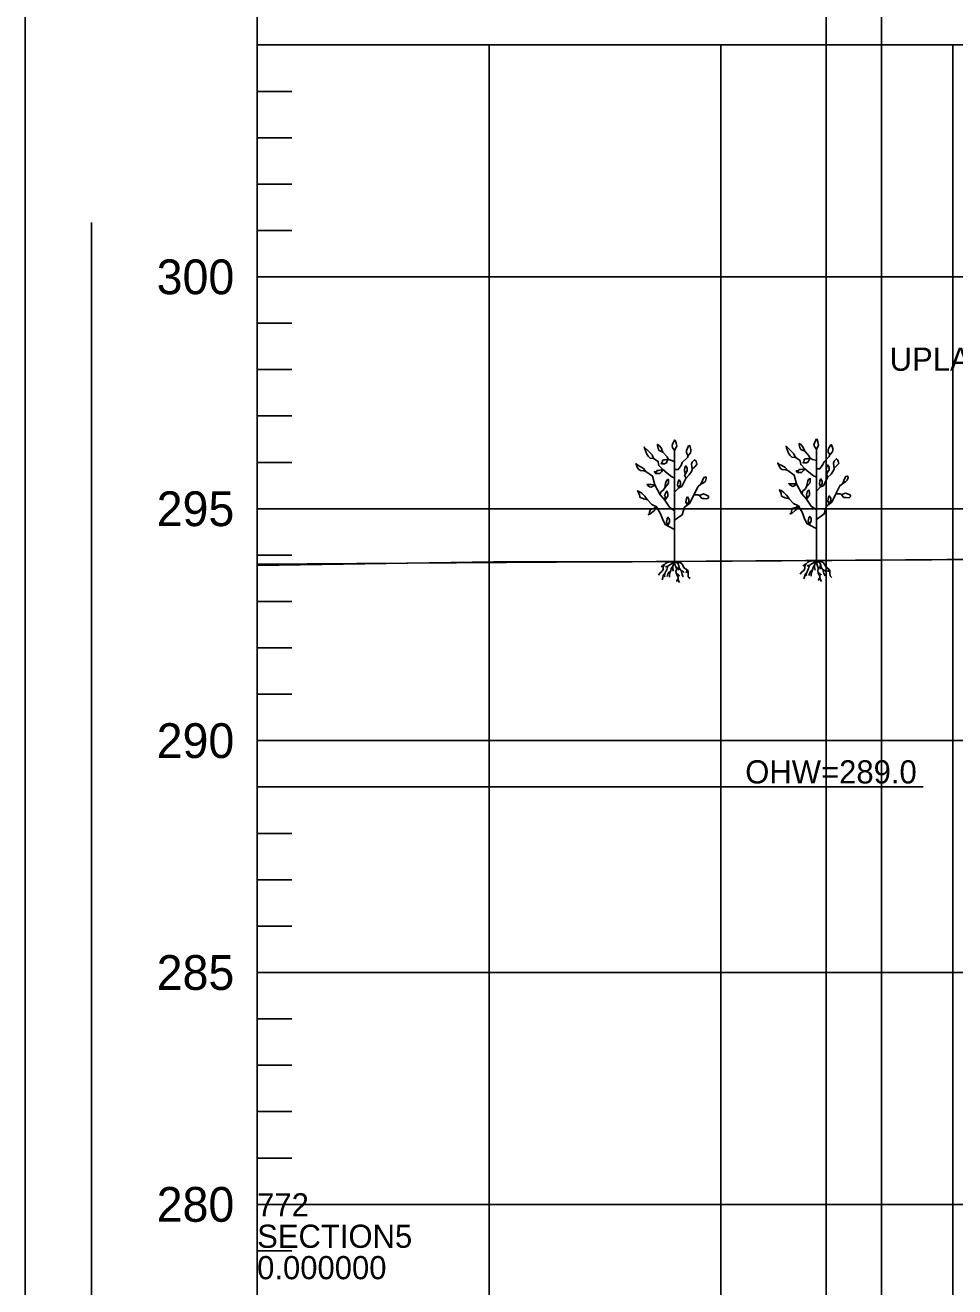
# Model space of a CAD drawing. Extents: x 1578769 to 1579225, y 724002 to 724828.
# Drawn here: x 1578822.77 to 1578842.81, y 724530.2 to 724557.4 of the extents above; entities that cross this region are included whole.
import ezdxf

# ---------------------------------------------------------------- set-up
doc = ezdxf.new("R2010")
doc.units = 0
for name, color, linetype in [('1', 7, 'Continuous'), ('Default', 7, 'Continuous'), ('Old_Level_1', 7, 'Continuous'), ('Old_Level_41', 7, 'Continuous'), ('Old_Level_42', 7, 'Continuous'), ('R_Exist Surface', 7, 'Continuous')]:
    doc.layers.add(name, color=color, linetype=linetype)

msp = doc.modelspace()

# ---------------------------------------------------------------- linework, layer by layer
at = {"layer": '1'}
for p, q in [((1578836.768, 724545.835), (1578836.768, 724548.235)), ((1578839.826, 724545.855), (1578839.826, 724548.255)), ((1578836.773, 724545.83), (1578836.775, 724545.834)), ((1578839.83, 724545.85), (1578839.832, 724545.854)), ((1578827.766, 724540.976), (1578842.126, 724540.976))]:
    msp.add_line(p, q, dxfattribs=at)
for points in [[(1578836.768, 724548.235), (1578836.724, 724548.299), (1578836.711, 724548.324), (1578836.724, 724548.374), (1578836.737, 724548.4), (1578836.762, 724548.456), (1578836.781, 724548.45), (1578836.8, 724548.4), (1578836.806, 724548.362), (1578836.812, 724548.324)], [(1578839.826, 724548.255), (1578839.781, 724548.319), (1578839.769, 724548.344), (1578839.781, 724548.394), (1578839.794, 724548.42), (1578839.819, 724548.476), (1578839.838, 724548.47), (1578839.857, 724548.42), (1578839.863, 724548.382), (1578839.87, 724548.344)], [(1578836.314, 724548.059), (1578836.238, 724548.065), (1578836.194, 724548.109), (1578836.169, 724548.153), (1578836.125, 724548.267), (1578836.112, 724548.305), (1578836.188, 724548.235), (1578836.232, 724548.191), (1578836.282, 724548.141)], [(1578836.516, 724548.197), (1578836.434, 724548.235), (1578836.409, 724548.273), (1578836.396, 724548.336), (1578836.396, 724548.362), (1578836.434, 724548.343), (1578836.478, 724548.292)], [(1578839.371, 724548.079), (1578839.295, 724548.085), (1578839.251, 724548.129), (1578839.226, 724548.173), (1578839.182, 724548.287), (1578839.169, 724548.325), (1578839.245, 724548.255), (1578839.289, 724548.211), (1578839.34, 724548.161)], [(1578839.573, 724548.217), (1578839.491, 724548.255), (1578839.466, 724548.293), (1578839.453, 724548.356), (1578839.453, 724548.382), (1578839.491, 724548.363), (1578839.535, 724548.312)], [(1578836.629, 724548.046), (1578836.561, 724548.031), (1578836.532, 724548.031), (1578836.504, 724548.022), (1578836.504, 724547.984), (1578836.475, 724547.955), (1578836.494, 724547.945), (1578836.551, 724547.945), (1578836.589, 724547.964), (1578836.609, 724548.012)], [(1578839.687, 724548.066), (1578839.618, 724548.051), (1578839.589, 724548.051), (1578839.561, 724548.042), (1578839.561, 724548.004), (1578839.532, 724547.975), (1578839.551, 724547.965), (1578839.609, 724547.965), (1578839.647, 724547.984), (1578839.666, 724548.032)], [(1578836.516, 724547.819), (1578836.475, 724547.812), (1578836.418, 724547.802), (1578836.389, 724547.802), (1578836.379, 724547.773), (1578836.332, 724547.773), (1578836.36, 724547.735), (1578836.399, 724547.735), (1578836.446, 724547.735), (1578836.484, 724547.773)], [(1578839.573, 724547.839), (1578839.532, 724547.832), (1578839.475, 724547.822), (1578839.446, 724547.822), (1578839.437, 724547.793), (1578839.389, 724547.793), (1578839.418, 724547.755), (1578839.456, 724547.755), (1578839.504, 724547.755), (1578839.542, 724547.793)], [(1578839.611, 724547.447), (1578839.63, 724547.542), (1578839.643, 724547.58), (1578839.649, 724547.599), (1578839.674, 724547.624), (1578839.693, 724547.624), (1578839.693, 724547.554), (1578839.68, 724547.529)], [(1578836.179, 724547.171), (1578836.093, 724547.191), (1578836.017, 724547.229), (1578836.007, 724547.286), (1578835.969, 724547.363), (1578836.026, 724547.334), (1578836.064, 724547.305), (1578836.122, 724547.248), (1578836.15, 724547.21)], [(1578836.554, 724547.162), (1578836.561, 724547.238), (1578836.551, 724547.257), (1578836.57, 724547.315), (1578836.599, 724547.353), (1578836.609, 724547.353), (1578836.618, 724547.296), (1578836.618, 724547.248)], [(1578836.554, 724547.427), (1578836.573, 724547.522), (1578836.585, 724547.56), (1578836.592, 724547.579), (1578836.617, 724547.604), (1578836.636, 724547.604), (1578836.636, 724547.534), (1578836.623, 724547.509)], [(1578839.236, 724547.191), (1578839.15, 724547.211), (1578839.074, 724547.249), (1578839.064, 724547.306), (1578839.026, 724547.383), (1578839.084, 724547.354), (1578839.122, 724547.325), (1578839.179, 724547.268), (1578839.208, 724547.23)], [(1578839.611, 724547.182), (1578839.618, 724547.258), (1578839.609, 724547.277), (1578839.628, 724547.335), (1578839.656, 724547.373), (1578839.666, 724547.373), (1578839.675, 724547.316), (1578839.675, 724547.268)], [(1578836.379, 724547.019), (1578836.322, 724546.98), (1578836.246, 724546.961), (1578836.227, 724546.904), (1578836.227, 724546.866), (1578836.198, 724546.847), (1578836.236, 724546.856), (1578836.313, 724546.923), (1578836.322, 724546.923), (1578836.379, 724546.99)], [(1578839.437, 724547.039), (1578839.379, 724547), (1578839.303, 724546.981), (1578839.284, 724546.924), (1578839.284, 724546.886), (1578839.255, 724546.867), (1578839.294, 724546.876), (1578839.37, 724546.943), (1578839.379, 724546.943), (1578839.437, 724547.01)]]:
    msp.add_lwpolyline(points, close=True, dxfattribs=at)
for points in [[(1578836.768, 724547.995), (1578836.68, 724548.021), (1578836.629, 724548.046), (1578836.604, 724548.096), (1578836.528, 724548.185), (1578836.516, 724548.197)], [(1578837.055, 724548.122), (1578837.024, 724548.179), (1578837.024, 724548.235), (1578837.043, 724548.28), (1578837.068, 724548.33), (1578837.093, 724548.336), (1578837.119, 724548.254), (1578837.119, 724548.216), (1578837.112, 724548.185), (1578837.062, 724548.122)], [(1578839.826, 724548.015), (1578839.737, 724548.041), (1578839.687, 724548.066), (1578839.661, 724548.116), (1578839.586, 724548.205), (1578839.573, 724548.217)], [(1578840.113, 724548.142), (1578840.081, 724548.199), (1578840.081, 724548.255), (1578840.1, 724548.3), (1578840.125, 724548.35), (1578840.151, 724548.356), (1578840.176, 724548.274), (1578840.176, 724548.236), (1578840.169, 724548.205), (1578840.119, 724548.142)], [(1578836.15, 724547.781), (1578836.106, 724547.793), (1578836.03, 724547.8), (1578835.998, 724547.819), (1578835.96, 724547.875), (1578835.935, 724547.939), (1578835.935, 724547.945), (1578835.973, 724547.913), (1578836.024, 724547.888), (1578836.093, 724547.844), (1578836.15, 724547.781)], [(1578836.756, 724547.642), (1578836.705, 724547.667), (1578836.604, 724547.743), (1578836.516, 724547.819), (1578836.427, 724547.907), (1578836.415, 724547.983), (1578836.415, 724547.995), (1578836.314, 724548.059)], [(1578836.768, 724547.819), (1578836.844, 724547.819), (1578836.907, 724547.907), (1578836.932, 724547.97), (1578837.046, 724548.084), (1578837.059, 724548.122)], [(1578837.002, 724547.73), (1578836.977, 724547.793), (1578836.989, 724547.869), (1578837.008, 724547.901), (1578837.04, 724547.85), (1578837.04, 724547.793), (1578837.002, 724547.73)], [(1578837.147, 724547.819), (1578837.134, 724547.939), (1578837.147, 724547.983), (1578837.197, 724548.033), (1578837.229, 724548.002), (1578837.248, 724547.932), (1578837.204, 724547.882), (1578837.147, 724547.831)], [(1578839.207, 724547.801), (1578839.163, 724547.813), (1578839.087, 724547.82), (1578839.056, 724547.839), (1578839.018, 724547.895), (1578838.992, 724547.959), (1578838.992, 724547.965), (1578839.03, 724547.933), (1578839.081, 724547.908), (1578839.15, 724547.864), (1578839.207, 724547.801)], [(1578839.813, 724547.662), (1578839.762, 724547.687), (1578839.661, 724547.763), (1578839.573, 724547.839), (1578839.485, 724547.927), (1578839.472, 724548.003), (1578839.472, 724548.015), (1578839.371, 724548.079)], [(1578839.826, 724547.839), (1578839.901, 724547.839), (1578839.964, 724547.927), (1578839.99, 724547.99), (1578840.103, 724548.104), (1578840.116, 724548.142)], [(1578840.059, 724547.75), (1578840.034, 724547.813), (1578840.046, 724547.889), (1578840.065, 724547.921), (1578840.097, 724547.87), (1578840.097, 724547.813), (1578840.059, 724547.75)], [(1578840.204, 724547.839), (1578840.192, 724547.959), (1578840.204, 724548.003), (1578840.255, 724548.053), (1578840.286, 724548.022), (1578840.305, 724547.952), (1578840.261, 724547.902), (1578840.204, 724547.851)], [(1578836.768, 724546.934), (1578836.655, 724547.01), (1578836.554, 724547.162), (1578836.453, 724547.275), (1578836.339, 724547.49), (1578836.289, 724547.68), (1578836.15, 724547.781)], [(1578836.768, 724547.351), (1578836.781, 724547.351), (1578836.857, 724547.427), (1578836.92, 724547.452), (1578837.008, 724547.629), (1578837.084, 724547.705), (1578837.134, 724547.781), (1578837.147, 724547.819)], [(1578837.008, 724547.629), (1578837.002, 724547.667), (1578836.983, 724547.692), (1578837.002, 724547.73)], [(1578837.336, 724547.503), (1578837.368, 724547.585), (1578837.399, 724547.648), (1578837.444, 724547.661), (1578837.45, 724547.629), (1578837.431, 724547.572), (1578837.393, 724547.534), (1578837.336, 724547.503)], [(1578839.826, 724546.954), (1578839.712, 724547.03), (1578839.611, 724547.182), (1578839.51, 724547.295), (1578839.396, 724547.51), (1578839.346, 724547.7), (1578839.207, 724547.801)], [(1578839.826, 724547.371), (1578839.838, 724547.371), (1578839.914, 724547.447), (1578839.977, 724547.472), (1578840.065, 724547.649), (1578840.141, 724547.725), (1578840.192, 724547.801), (1578840.204, 724547.839)], [(1578839.914, 724547.447), (1578839.889, 724547.51), (1578839.901, 724547.586), (1578839.92, 724547.618), (1578839.952, 724547.567), (1578839.952, 724547.51), (1578839.914, 724547.447)], [(1578840.065, 724547.649), (1578840.059, 724547.687), (1578840.04, 724547.712), (1578840.059, 724547.75)], [(1578840.394, 724547.523), (1578840.425, 724547.605), (1578840.457, 724547.668), (1578840.501, 724547.681), (1578840.507, 724547.649), (1578840.488, 724547.592), (1578840.45, 724547.554), (1578840.394, 724547.523)], [(1578836.339, 724547.49), (1578836.265, 724547.496), (1578836.208, 724547.496), (1578836.169, 724547.496), (1578836.189, 724547.477), (1578836.227, 724547.449), (1578836.265, 724547.439), (1578836.341, 724547.487)], [(1578836.453, 724547.275), (1578836.472, 724547.339), (1578836.522, 724547.376), (1578836.554, 724547.427)], [(1578836.768, 724546.727), (1578836.932, 724546.846), (1578836.983, 724547.01), (1578837.096, 724547.099), (1578837.185, 724547.275), (1578837.273, 724547.452), (1578837.336, 724547.503)], [(1578836.857, 724547.427), (1578836.831, 724547.49), (1578836.844, 724547.566), (1578836.863, 724547.598), (1578836.894, 724547.547), (1578836.894, 724547.49), (1578836.857, 724547.427)], [(1578839.396, 724547.51), (1578839.322, 724547.516), (1578839.265, 724547.516), (1578839.227, 724547.516), (1578839.246, 724547.497), (1578839.284, 724547.469), (1578839.322, 724547.459), (1578839.399, 724547.507)], [(1578839.51, 724547.295), (1578839.529, 724547.359), (1578839.579, 724547.396), (1578839.611, 724547.447)], [(1578839.826, 724546.747), (1578839.99, 724546.866), (1578840.04, 724547.03), (1578840.154, 724547.119), (1578840.242, 724547.295), (1578840.33, 724547.472), (1578840.394, 724547.523)], [(1578836.771, 724546.531), (1578836.733, 724546.541), (1578836.656, 724546.589), (1578836.561, 724546.636), (1578836.504, 724546.761), (1578836.465, 724546.866), (1578836.379, 724547.019), (1578836.274, 724547.066), (1578836.179, 724547.171), (1578836.179, 724547.171)], [(1578837.038, 724547.061), (1578837.012, 724547.125), (1578837.025, 724547.2), (1578837.044, 724547.232), (1578837.075, 724547.181), (1578837.075, 724547.125), (1578837.038, 724547.061)], [(1578837.185, 724547.275), (1578837.248, 724547.275), (1578837.273, 724547.275), (1578837.305, 724547.263)], [(1578837.305, 724547.263), (1578837.393, 724547.294), (1578837.456, 724547.269), (1578837.5, 724547.25), (1578837.5, 724547.219), (1578837.481, 724547.2), (1578837.45, 724547.193), (1578837.406, 724547.2), (1578837.355, 724547.2), (1578837.305, 724547.263)], [(1578839.828, 724546.551), (1578839.79, 724546.561), (1578839.714, 724546.609), (1578839.618, 724546.656), (1578839.561, 724546.781), (1578839.523, 724546.886), (1578839.437, 724547.039), (1578839.332, 724547.086), (1578839.236, 724547.191), (1578839.236, 724547.191)], [(1578840.095, 724547.081), (1578840.07, 724547.145), (1578840.082, 724547.22), (1578840.101, 724547.252), (1578840.133, 724547.201), (1578840.133, 724547.145), (1578840.095, 724547.081)], [(1578840.242, 724547.295), (1578840.305, 724547.295), (1578840.33, 724547.295), (1578840.362, 724547.283)], [(1578840.362, 724547.283), (1578840.45, 724547.314), (1578840.513, 724547.289), (1578840.558, 724547.27), (1578840.558, 724547.239), (1578840.539, 724547.22), (1578840.507, 724547.213), (1578840.463, 724547.22), (1578840.412, 724547.22), (1578840.362, 724547.283)], [(1578839.675, 724546.642), (1578839.65, 724546.705), (1578839.662, 724546.781), (1578839.681, 724546.812), (1578839.713, 724546.762), (1578839.713, 724546.705), (1578839.675, 724546.642)], [(1578836.618, 724546.622), (1578836.592, 724546.685), (1578836.605, 724546.761), (1578836.624, 724546.792), (1578836.655, 724546.742), (1578836.655, 724546.685), (1578836.618, 724546.622)], [(1578836.768, 724545.835), (1578836.717, 724545.83), (1578836.701, 724545.834), (1578836.643, 724545.826), (1578836.608, 724545.818), (1578836.581, 724545.802), (1578836.55, 724545.771), (1578836.527, 724545.736), (1578836.519, 724545.702), (1578836.519, 724545.67), (1578836.503, 724545.636), (1578836.492, 724545.62), (1578836.453, 724545.593), (1578836.418, 724545.546)], [(1578836.55, 724545.771), (1578836.507, 724545.752), (1578836.492, 724545.729), (1578836.48, 724545.721)], [(1578836.768, 724545.835), (1578836.701, 724545.787), (1578836.663, 724545.768), (1578836.624, 724545.736), (1578836.604, 724545.698), (1578836.597, 724545.667), (1578836.558, 724545.581), (1578836.523, 724545.538), (1578836.511, 724545.488), (1578836.496, 724545.445)], [(1578836.624, 724545.736), (1578836.581, 724545.729), (1578836.577, 724545.713)], [(1578836.768, 724545.835), (1578836.728, 724545.74), (1578836.694, 724545.686), (1578836.682, 724545.636), (1578836.666, 724545.597), (1578836.655, 724545.538), (1578836.655, 724545.5)], [(1578836.728, 724545.74), (1578836.728, 724545.686), (1578836.732, 724545.663), (1578836.744, 724545.632)], [(1578836.768, 724545.835), (1578836.852, 724545.819), (1578836.895, 724545.806), (1578836.922, 724545.787), (1578836.95, 724545.748), (1578836.969, 724545.702), (1578837.035, 724545.655), (1578837.058, 724545.628), (1578837.058, 724545.569), (1578837.062, 724545.511), (1578837.101, 724545.472)], [(1578836.768, 724545.835), (1578836.837, 724545.799), (1578836.86, 724545.744), (1578836.872, 724545.69), (1578836.907, 724545.643), (1578836.93, 724545.558), (1578836.953, 724545.507)], [(1578836.768, 724545.835), (1578836.775, 724545.771), (1578836.787, 724545.744), (1578836.798, 724545.705), (1578836.806, 724545.69), (1578836.806, 724545.659), (1578836.794, 724545.62), (1578836.806, 724545.573), (1578836.822, 724545.538), (1578836.841, 724545.5), (1578836.841, 724545.465), (1578836.853, 724545.422), (1578836.876, 724545.387)], [(1578836.86, 724545.744), (1578836.849, 724545.713), (1578836.837, 724545.698), (1578836.856, 724545.651)], [(1578839.826, 724545.855), (1578839.774, 724545.85), (1578839.759, 724545.854), (1578839.7, 724545.846), (1578839.665, 724545.838), (1578839.638, 724545.822), (1578839.607, 724545.791), (1578839.584, 724545.756), (1578839.576, 724545.722), (1578839.576, 724545.69), (1578839.561, 724545.656), (1578839.549, 724545.64), (1578839.51, 724545.613), (1578839.475, 724545.566)], [(1578839.607, 724545.791), (1578839.565, 724545.772), (1578839.549, 724545.749), (1578839.537, 724545.741)], [(1578839.826, 724545.855), (1578839.759, 724545.807), (1578839.72, 724545.788), (1578839.681, 724545.756), (1578839.662, 724545.718), (1578839.654, 724545.687), (1578839.615, 724545.601), (1578839.58, 724545.558), (1578839.569, 724545.508), (1578839.553, 724545.465)], [(1578839.681, 724545.756), (1578839.638, 724545.749), (1578839.634, 724545.733)], [(1578839.826, 724545.855), (1578839.786, 724545.76), (1578839.751, 724545.706), (1578839.739, 724545.656), (1578839.724, 724545.617), (1578839.712, 724545.558), (1578839.712, 724545.52)], [(1578839.786, 724545.76), (1578839.786, 724545.706), (1578839.79, 724545.683), (1578839.801, 724545.652)], [(1578839.826, 724545.855), (1578839.909, 724545.839), (1578839.953, 724545.826), (1578839.98, 724545.807), (1578840.007, 724545.768), (1578840.026, 724545.722), (1578840.092, 724545.675), (1578840.116, 724545.648), (1578840.116, 724545.589), (1578840.119, 724545.531), (1578840.158, 724545.492)], [(1578839.826, 724545.855), (1578839.894, 724545.819), (1578839.918, 724545.764), (1578839.929, 724545.71), (1578839.964, 724545.663), (1578839.987, 724545.578), (1578840.011, 724545.527)], [(1578839.826, 724545.855), (1578839.832, 724545.791), (1578839.844, 724545.764), (1578839.856, 724545.725), (1578839.863, 724545.71), (1578839.863, 724545.679), (1578839.852, 724545.64), (1578839.863, 724545.593), (1578839.879, 724545.558), (1578839.898, 724545.52), (1578839.898, 724545.485), (1578839.91, 724545.442), (1578839.933, 724545.407)], [(1578839.918, 724545.764), (1578839.906, 724545.733), (1578839.894, 724545.718), (1578839.914, 724545.671)], [(1578836.558, 724545.581), (1578836.55, 724545.527), (1578836.554, 724545.511)], [(1578836.682, 724545.636), (1578836.635, 724545.597), (1578836.631, 724545.577), (1578836.624, 724545.573), (1578836.604, 724545.515)], [(1578836.806, 724545.573), (1578836.841, 724545.558), (1578836.864, 724545.538), (1578836.868, 724545.523)], [(1578836.841, 724545.465), (1578836.814, 724545.43), (1578836.818, 724545.406)], [(1578836.907, 724545.643), (1578836.942, 724545.624), (1578836.961, 724545.612), (1578836.973, 724545.601)], [(1578837.035, 724545.655), (1578837.023, 724545.616), (1578837.019, 724545.597)], [(1578839.615, 724545.601), (1578839.607, 724545.547), (1578839.611, 724545.531)], [(1578839.739, 724545.656), (1578839.693, 724545.617), (1578839.689, 724545.597), (1578839.681, 724545.593), (1578839.662, 724545.535)], [(1578839.863, 724545.593), (1578839.898, 724545.578), (1578839.922, 724545.558), (1578839.925, 724545.543)], [(1578839.898, 724545.485), (1578839.871, 724545.45), (1578839.875, 724545.426)], [(1578839.964, 724545.663), (1578839.999, 724545.644), (1578840.019, 724545.632), (1578840.03, 724545.621)], [(1578840.092, 724545.675), (1578840.081, 724545.636), (1578840.077, 724545.617)]]:
    msp.add_lwpolyline(points, dxfattribs=at)
at = {"layer": 'Default'}
for p, q in [((1578827.766, 724526.976), (1578827.766, 724776.976)), ((1578841.23, 724437.474), (1578841.23, 724687.474)), ((1578840.032, 724387.146), (1578840.032, 724637.146)), ((1578824.194, 724303.15), (1578824.194, 724553.15))]:
    msp.add_line(p, q, dxfattribs=at)
msp.add_lwpolyline([(1578827.766, 724545.778), (1578841.746, 724545.874), (1578855.126, 724545.979), (1578880.286, 724546.165), (1578882.476, 724543.201), (1578888.466, 724535.266), (1578896.646, 724531.004), (1578897.956, 724530.207), (1578900.066, 724530.294), (1578933.126, 724531.692), (1578958.306, 724535.052), (1578969.886, 724536.54), (1578983.926, 724537.607), (1579000.856, 724538.888), (1579028.426, 724540.267), (1579057.456, 724541.791), (1579058.756, 724541.812)], dxfattribs=at)
at = {"layer": 'Old_Level_1'}
for points in [[(1578822.766, 724559.476), (1578930.266, 724559.476), (1578930.266, 724524.476), (1578822.766, 724524.476)], [(1578827.766, 724556.976), (1578927.766, 724556.976), (1578927.766, 724526.976), (1578827.766, 724526.976)]]:
    msp.add_lwpolyline(points, close=True, dxfattribs=at)
at = {"layer": 'Old_Level_41'}
for p, q in [((1578832.766, 724526.976), (1578832.766, 724556.976)), ((1578837.766, 724556.976), (1578837.766, 724526.976)), ((1578842.766, 724526.976), (1578842.766, 724556.976)), ((1578827.766, 724554.476), (1578827.766, 724526.976))]:
    msp.add_line(p, q, dxfattribs=at)
for points in [[(1578927.766, 724551.976), (1578827.766, 724551.976)], [(1578927.766, 724546.976), (1578827.766, 724546.976)], [(1578827.766, 724541.976), (1578888.475, 724541.976)], [(1578927.766, 724536.976), (1578827.766, 724536.976)], [(1578827.766, 724531.976), (1578927.766, 724531.976)]]:
    msp.add_lwpolyline(points, dxfattribs=at)
at = {"layer": 'Old_Level_42'}
for p, q in [((1578827.766, 724555.976), (1578828.516, 724555.976)), ((1578827.766, 724554.976), (1578828.516, 724554.976)), ((1578827.766, 724553.976), (1578828.516, 724553.976)), ((1578827.766, 724552.976), (1578828.516, 724552.976)), ((1578827.766, 724550.976), (1578828.516, 724550.976)), ((1578827.766, 724549.976), (1578828.516, 724549.976)), ((1578827.766, 724548.976), (1578828.516, 724548.976)), ((1578827.766, 724547.976), (1578828.516, 724547.976)), ((1578827.766, 724545.976), (1578828.516, 724545.976)), ((1578827.766, 724544.976), (1578828.516, 724544.976)), ((1578827.766, 724543.976), (1578828.516, 724543.976)), ((1578827.766, 724542.976), (1578828.516, 724542.976)), ((1578827.766, 724540.976), (1578828.516, 724540.976)), ((1578827.766, 724539.976), (1578828.516, 724539.976)), ((1578827.766, 724538.976), (1578828.516, 724538.976)), ((1578827.766, 724537.976), (1578828.516, 724537.976)), ((1578827.766, 724535.976), (1578828.516, 724535.976)), ((1578827.766, 724534.976), (1578828.516, 724534.976)), ((1578827.766, 724533.976), (1578828.516, 724533.976)), ((1578827.766, 724532.976), (1578828.516, 724532.976)), ((1578827.766, 724530.976), (1578828.516, 724530.976))]:
    msp.add_line(p, q, dxfattribs=at)
at = {"layer": 'R_Exist Surface'}
msp.add_lwpolyline([(1578827.766, 724545.753), (1578832.87, 724545.829), (1578835.855, 724545.829), (1578849.85, 724545.921), (1578865.935, 724546.072), (1578876.895, 724546.144), (1578879.811, 724546.167), (1578880.852, 724545.469), (1578882.795, 724542.798), (1578885.883, 724538.793), (1578888.763, 724535.059), (1578896.849, 724530.913), (1578897.81, 724530.272), (1578902.771, 724530.386), (1578927.766, 724531.445)], dxfattribs=at)

# ---------------------------------------------------------------- texts
at = {"layer": '1'}
for s, height, p in [('300', 0.75, (1578825.6, 724551.601)), ('UPLAND', 0.5, (1578841.404, 724549.951)), ('295', 0.75, (1578825.6, 724546.601)), ('290', 0.75, (1578825.6, 724541.601)), ('OHW=289.0', 0.5, (1578838.29, 724541.052)), ('285', 0.75, (1578825.6, 724536.601)), ('280', 0.75, (1578825.6, 724531.601))]:
    msp.add_text(s, height=height, dxfattribs=at).set_placement(p)
at = {"layer": 'Default'}
for s, p in [('772', (1578827.766, 724531.716)), ('SECTION5', (1578827.766, 724531.039)), ('0.000000', (1578827.766, 724530.362))]:
    msp.add_text(s, height=0.5, dxfattribs=at).set_placement(p)

doc.saveas('drawing.dxf')
